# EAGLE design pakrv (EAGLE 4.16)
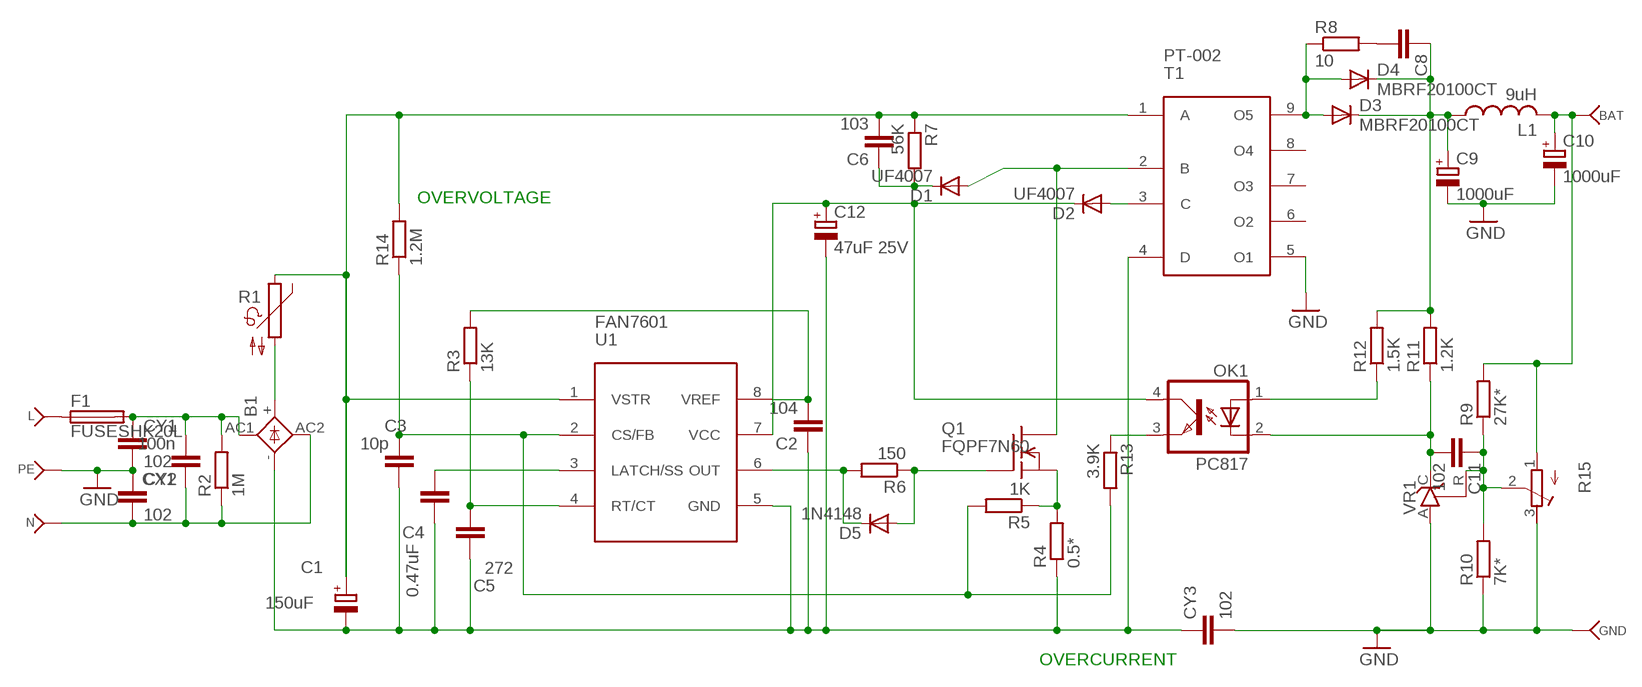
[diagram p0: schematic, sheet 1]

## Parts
B1  2KBB-R  [2KBB-R]
BAT  PINA  [PIN2]
C1  150uF  CPOL-EUE7.5-16  [E7,5-16]
C2  104  C-EU050-024X044  [C050-024X044]
C3  10p  C-EU050-024X044  [C050-024X044]
C4  0.47uF  C-EU050-024X044  [C050-024X044]
C5  272  C-EU050-024X044  [C050-024X044]
C6  103  C-EU075-032X103  [C075-032X103]
C8  C-EU050-024X044  [C050-024X044]
C9  1000uF  CPOL-EUE5-8.5  [E5-8,5]
C10  1000uF  CPOL-EUE5-8.5  [E5-8,5]
C11  102  C-EU025-024X044  [C025-024X044]
C12  47uF 25V  CPOL-EUE2.5-6  [E2,5-6]
CX1  100n  CXXC10B5  [XC10B5]
CY1  102  CYYC7B5  [YC7B5]
CY2  102  CYYC7B5  [YC7B5]
CY3  102  CYYC7B5  [YC7B5]
D1  UF4007  DIODE-DO07  [DO07]
D2  UF4007  DIODE-DO41-10  [DO41-10]
D3  MBRF20100CT  DIODE-DO220S  [DO220S]
D4  MBRF20100CT  DIODE-DO220S  [DO220S]
D5  1N4148  DIODE-DO35-10  [DO35-10]
F1  FUSESHK20L  [SHK20L]
GND  PINA  [PIN2]
L  PINA  [PIN2]
L1  9uH  L-US0207/7  [0207/7]
N  PINA  [PIN2]
OK1  PC817  [DIL04]
PE  PINA  [PIN2]
Q1  FQPF7N60  BUZ60  [TO220]
R1  B57164  [B57164]
R2  1M  R-EU_0207/15  [0207/15]
R3  13K  R-EU_0204/2V  [0204V]
R4  0.5*  R-EU_0207/10  [0207/10]
R5  1K  R-EU_0207/12  [0207/12]
R6  150  R-EU_0204/7  [0204/7]
R7  56K  R-EU_0414/5V  [0414V]
R8  10  R-EU_0204/2V  [0204V]
R9  27K*  R-EU_0204/5  [0204/5]
R10  7K*  R-EU_0204/5  [0204/5]
R11  1.2K  R-EU_0204/5  [0204/5]
R12  1.5K  R-EU_0204/5  [0204/5]
R13  3.9K  R-EU_0204/2V  [0204V]
R14  1.2M  R-EU_0204/2V  [0204V]
R15  R-TRIMM74X  [RTRIM74X]
T1  PT-002  [PT-002]
U1  FAN7601  [DIL08]
VR1  TL431CLP  [TO92-CLP]

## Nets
FEEDBACK: C3.2 R5.2 R13.2 R14.1 U1.2(CS/FB)
GATE: D5.A Q1.1(G) R6.1
GND: C9.- C10.- CY1.2 CY2.1 CY3.2 GND.P$1(P) PE.P$1(P) R10.1 R15.3(A) T1.5(O1) VR1.A
MINUS: B1.- C1.- C2.1 C3.1 C4.1 C5.1 C12.- CY3.1 R4.1 T1.4(D) U1.5(GND)
N$1: B1.+ R1.2
N$2: B1.AC1 CX1.2 CY1.1 F1.2A R2.2
N$5: B1.AC2 CX1.1 CY2.2 N.P$1(P) R2.1
N$6: D1.A Q1.2(D) T1.2(B)
N$7: C6.1 D1.C R7.2
N$8: C5.2 R3.1 U1.4(RT/CT)
N$9: C4.2 U1.3(LATCH/SS)
N$10: F1.1A L.P$1(P)
N$11: C2.2 R3.2 U1.8(VREF)
N$12: C11.2 OK1.2(C) R11.1 VR1.C
N$15: Q1.3(S) R4.2 R5.1
N$16: OK1.1(A) R12.1
N$17: C8.1 C9.+ D3.C D4.C L1.1 R11.2 R12.2
N$18: D2.A T1.3(C)
N$20: D3.A D4.A R8.1 T1.9(O5)
N$21: C11.1 R9.1 R10.2 R15.2(S) VR1.R
N$22: C8.2 R8.2
N$24: OK1.3(EMIT) R13.1
N$26: BAT.P$1(P) C10.+ L1.2 R9.2 R15.1(E)
OUT: D5.C R6.2 U1.6(OUT)
PLIUS: C1.+ C6.2 R1.1 R7.1 R14.2 T1.1(A) U1.1(VSTR)
VCC: C12.+ D2.C OK1.4(COL) U1.7(VCC)
Unconnected: T1.6(O2) T1.7(O3) T1.8(O4)

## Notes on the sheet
- OVERVOLTAGE
- OVERCURRENT

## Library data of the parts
B1 = rectifier:2KBB-R: RECTIFIER grid 3 x 5 mm
BAT GND L N PE = LevoROMS:PIN*: PIN
C1 C9 C10 C12 = rcl:CPOL-EU: POLARIZED CAPACITOR, European symbol
C2-C6 C8 C11 = rcl:C-EU: CAPACITOR, European symbol
CX1 = rcl:CX: X CAPACITOR
CY1-CY3 = rcl:CY: Y CAPACITOR
D1-D5 = diode:DIODE-: DIODE
F1 = fuse:FUSE: Fuse
L1 = rcl:L-US: INDUCTOR, American symbol
OK1 = optocoupler:PC817: SHARP OPTO COUPLER
Q1 = transistor-fet:BUZ60: N-Channel Enhancement MOSFET 400V; 5,5A; 1,0Ohm
R1 = ptc-ntc:B57164: SIEMENS NTC
R2-R14 = rcl:R-EU_: RESISTOR, European symbol
R15 = rcl:R-TRIMM: Trimm resistor
T1 = LG-trafo:PT-002
U1 = LevoROMS:FAN7601
VR1 = v-reg:TL431CLP: VOLTAGE REGULATOR

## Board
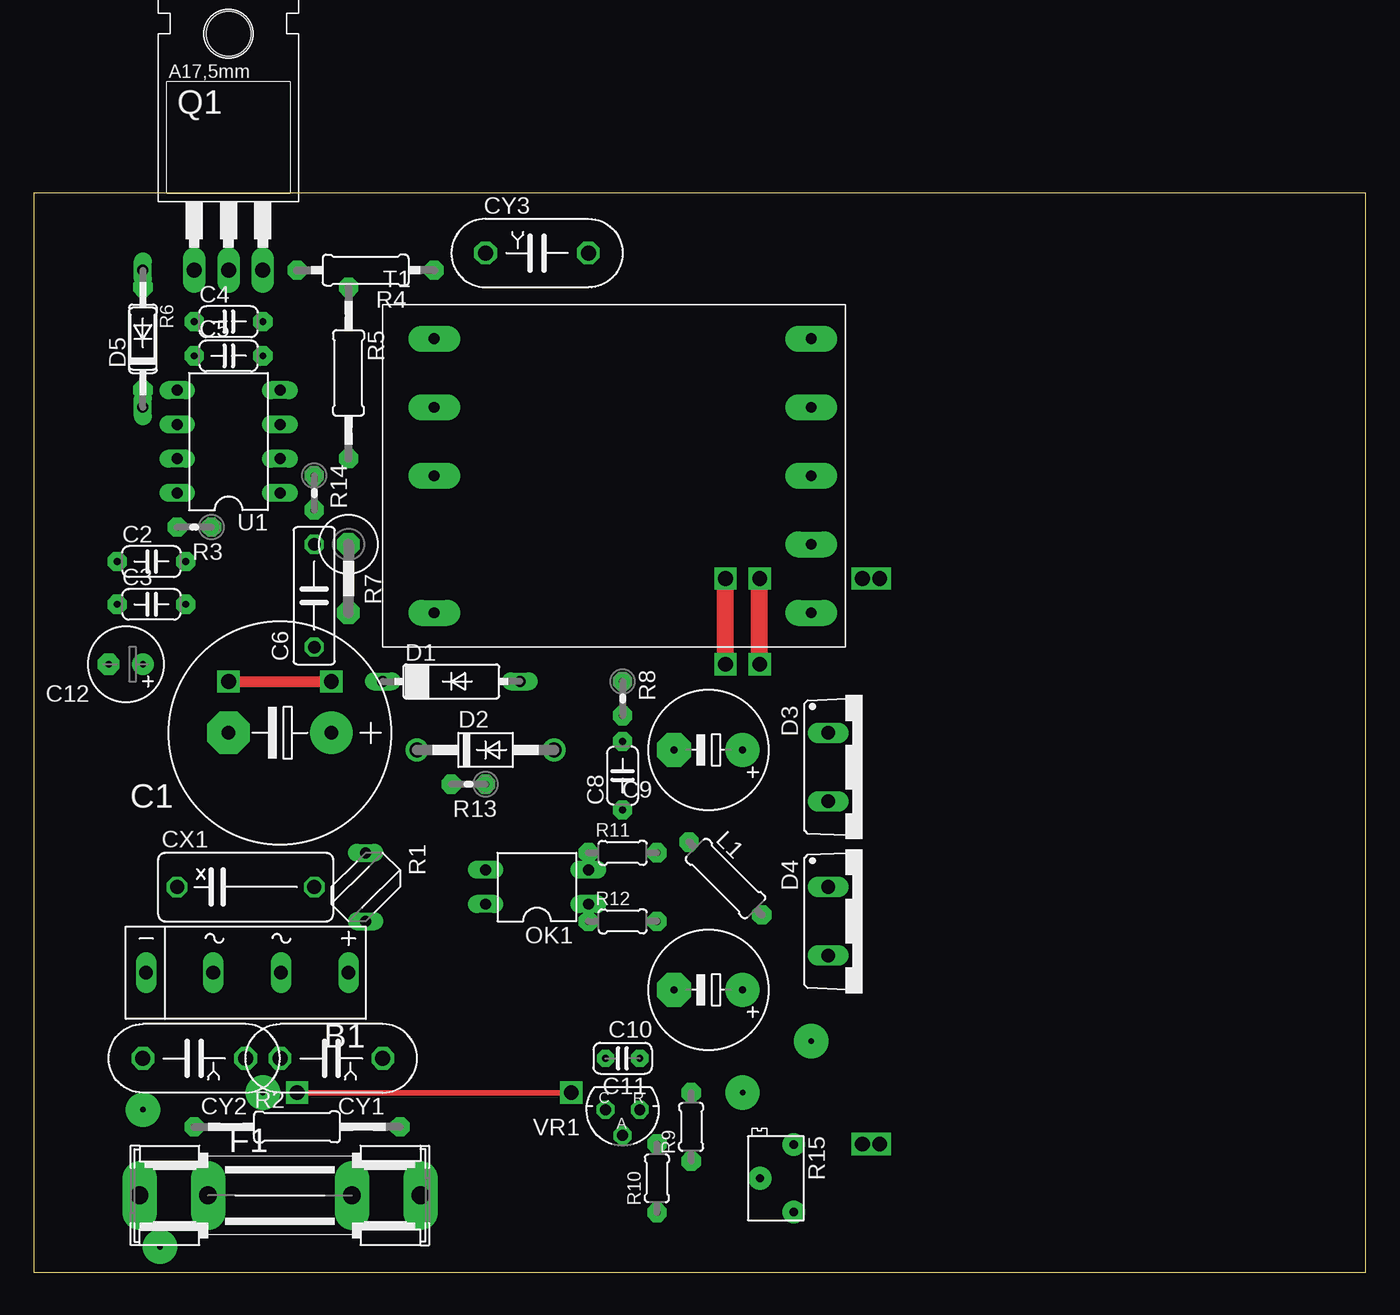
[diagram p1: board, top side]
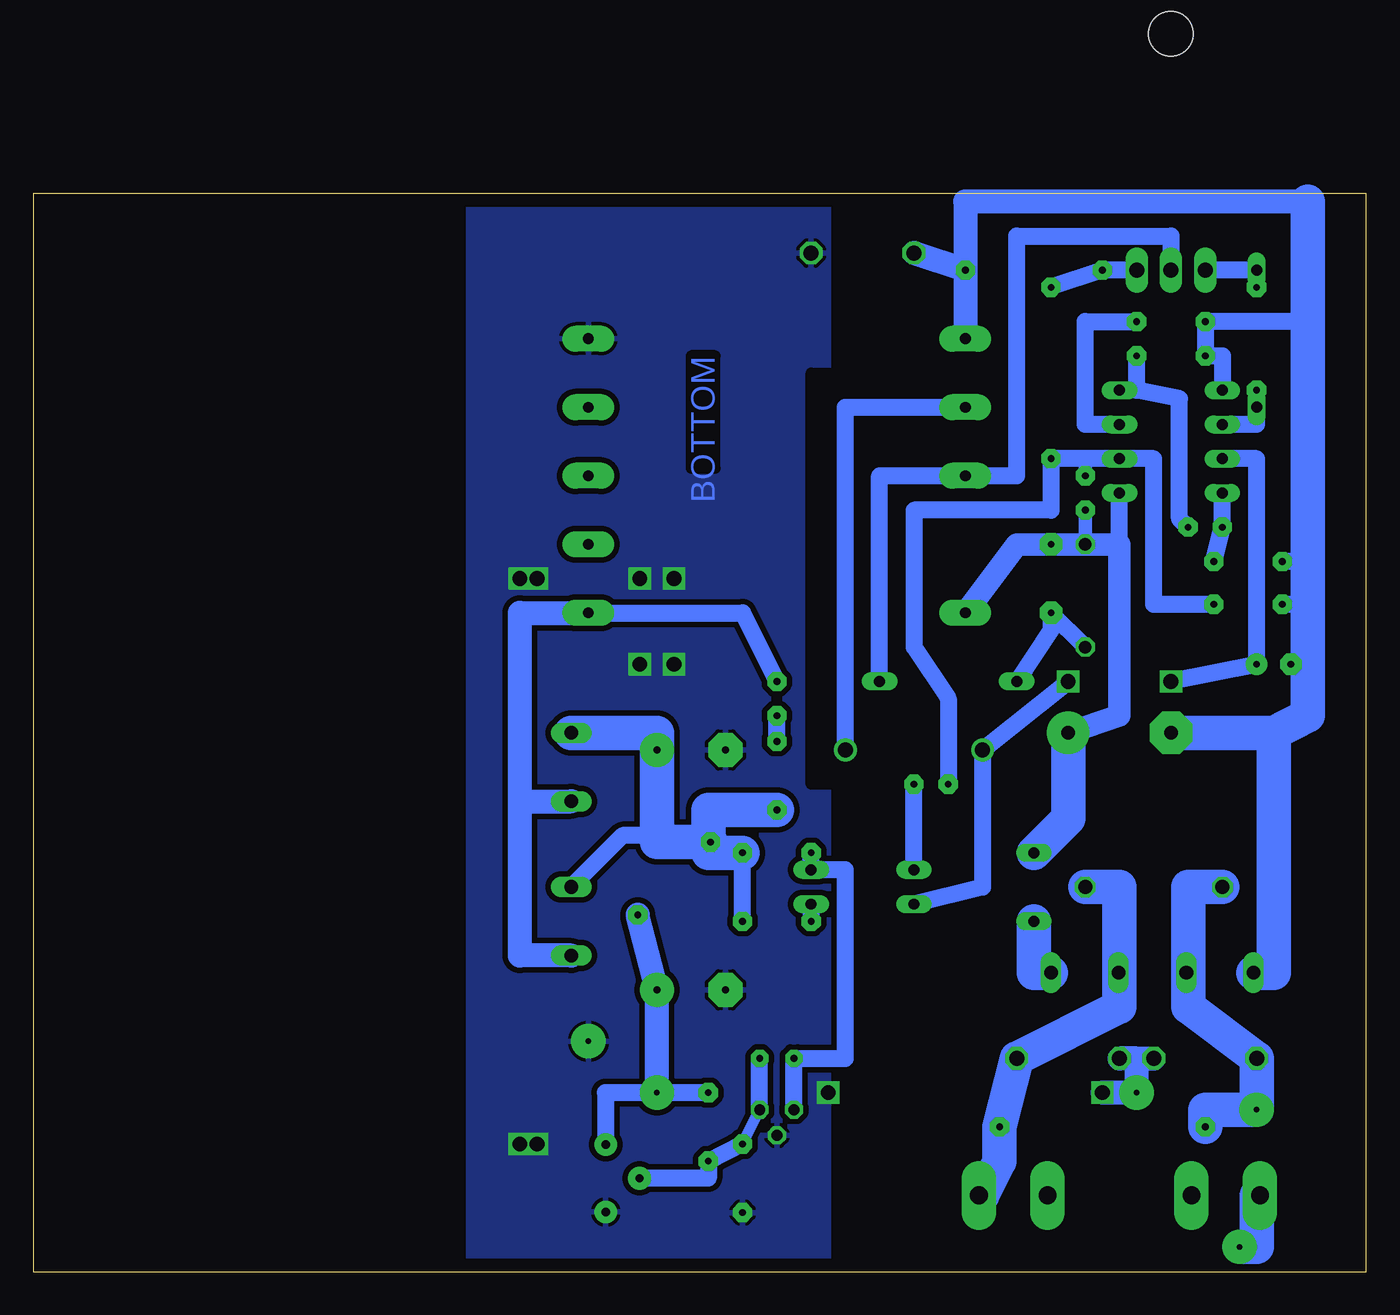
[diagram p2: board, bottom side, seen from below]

Size 98.73 x 80 mm. Coordinates in mm from the lower left corner, seen from the top.
Outline: 0,0 98.73,0 98.73,80 0,80 0,0
Copper layers (1*16): Top 0.035mm / dielectric 1.5mm / Bottom 0.035mm
Design rules "default": minimum track width 10mil, minimum drill 24mil, track to track 8mil, track to pad 8mil, pad to pad 8mil, via to via 8mil, smd to smd 8mil, copper to edge 40mil, drill to drill 8mil, minimum pad ring 10mil, minimum via ring 8mil, stop-mask expansion 4mil, vias tented up to drill 0mil, thermal gap 10mil
bRestrict: area 36,36.2 to 41.1,66.7

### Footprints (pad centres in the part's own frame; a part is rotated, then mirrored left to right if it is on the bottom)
2KBB-R = drill 1.016 long: + -7.62,0; - 7.391,0; AC1 -2.616,0; AC2 2.413,0
PIN2 = drill 0.406 pad 2.54 round: P$1 0,0
E7,5-16 = drill 1.016 pad 3.15 round: + -3.81,0 | drill 1.016 pad 3.15 octagon: - 3.81,0
C050-024X044 = drill 0.5 pad 1.422 octagon: 1 -2.54,0; 2 2.54,0
C075-032X103 = drill 0.914 octagon: 1 -3.81,0; 2 3.81,0
E5-8,5 = drill 0.5 pad 2.54 round: + -2.54,0 | drill 0.5 pad 2.54 octagon: - 2.54,0
C025-024X044 = drill 0.5 pad 1.27 octagon: 1 -1.27,0; 2 1.27,0
E2,5-6 = drill 0.5 pad 1.6 round: + -1.27,0 | drill 0.5 pad 1.6 octagon: - 1.27,0
XC10B5 = drill 1.016 octagon: 1 -5.08,0; 2 5.08,0
YC7B5 = drill 1.118 octagon: 1 -3.81,0; 2 3.81,0
DO07 = drill 0.813 long: A 5.08,0; C -5.08,0
DO41-10 = drill 1.118 round: A 5.08,0; C -5.08,0
DO220S = drill 1.016 long: A 2.54,-2.54; C -2.54,-2.54
DO35-10 = drill 0.813 long: A 5.08,0; C -5.08,0
SHK20L = drill 1.321 pad 2.54 long: 1A -10.414,0; 1B -5.334,0; 2A 10.414,0; 2B 5.334,0
0207/7 = drill 0.5 pad 1.422 octagon: 1 -3.81,0; 2 3.81,0
DIL04 = drill 0.813 long: 1 -1.27,-3.81; 2 1.27,-3.81; 3 1.27,3.81; 4 -1.27,3.81
TO220 = drill 1.118 long: 1 -2.54,-6.35; 2 0,-6.35; 3 2.54,-6.35 | hole 3.302: 0,11.176
B57164 = drill 0.813 long: 1 -2.54,0; 2 2.54,0
0207/15 = drill 0.5 pad 1.422 octagon: 1 -7.62,0; 2 7.62,0
0204V = drill 0.5 pad 1.422 octagon: 1 -1.27,0; 2 1.27,0
0207/10 = drill 0.5 pad 1.422 octagon: 1 -5.08,0; 2 5.08,0
0207/12 = drill 0.5 pad 1.422 octagon: 1 -6.35,0; 2 6.35,0
0204/7 = drill 0.5 pad 1.422 octagon: 1 -3.81,0; 2 3.81,0
0414V = drill 0.5 pad 1.676 octagon: 1 -2.54,0; 2 2.54,0
0204/5 = drill 0.5 pad 1.422 octagon: 1 -2.54,0; 2 2.54,0
RTRIM74X = drill 0.61 pad 1.676 round: 1 -1.25,-2.5; 2 1.25,0; 3 -1.25,2.5
PT-002 = drill 0.8 pad 1.93 long: 1 -3.81,-12.7; 2 -3.81,-2.54; 3 -3.81,2.54; 4 -3.81,7.62; 5 24.13,7.62; 6 24.13,2.54; 7 24.13,-2.54; 8 24.13,-7.62; 9 24.13,-12.7
DIL08 = drill 0.813 long: 1 -3.81,-3.81; 2 -1.27,-3.81; 3 1.27,-3.81; 4 3.81,-3.81; 5 3.81,3.81; 6 1.27,3.81; 7 -1.27,3.81; 8 -3.81,3.81
TO92-CLP = drill 0.813 octagon: A 0,1.905; C 1.27,0; R -1.27,0

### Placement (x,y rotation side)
B1  15.71,22.22 180 top
BAT  52.54,13.33 0 top
C1  18.25,40 180 top
C2  8.72,52.7 0 top
C3  8.72,49.53 0 top
C4  14.44,70.48 0 top
C5  14.44,67.94 0 top
C6  20.79,50.16 90 top
C8  43.65,36.83 90 top
C9  50,38.73 180 top
C10  50,20.95 180 top
C11  43.65,15.87 180 top
C12  6.82,45.08 180 top
CX1  15.71,28.57 0 top
CY1  22.06,15.87 180 top
CY2  11.9,15.87 180 top
CY3  37.3,75.56 0 top
D1  30.95,43.81 0 top
D2  33.49,38.73 0 top
D3  61.43,37.46 270 top
D4  61.43,26.03 270 top
D5  8.09,69.21 90 top
F1  18.25,5.71 0 top
GND  16.98,13.33 0 top
L  9.36,1.9 0 top
L1  51.27,29.2 315 top
N  8.09,12.06 0 top
OK1  37.3,28.57 90 top
PE  57.62,17.14 0 top
Q1  14.44,80.64 0 top
R1  24.6,28.57 270 top
R2  19.52,10.79 0 top
R3  11.9,55.24 180 top
R4  24.6,74.29 180 top
R5  23.33,66.67 270 top
R6  8.09,69.21 270 top
R7  23.33,51.43 270 top
R8  43.65,42.54 270 top
R9  48.73,10.79 90 top
R10  46.19,6.98 90 top
R11  43.65,31.11 0 top
R12  43.65,26.03 0 top
R13  32.22,36.19 180 top
R14  20.79,57.78 270 top
R15  55.08,6.98 180 top
T1  33.49,61.59 0 top
U1  14.44,61.59 90 top
VR1  43.65,12.06 180 top

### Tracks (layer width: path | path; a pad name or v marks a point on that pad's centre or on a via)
FEEDBACK
  Bottom 1.016: 20.79,60.32 R14.1
  Bottom 1.27: R13.2 30.95,42.54 33.49,46.35 33.49,56.51 23.33,56.51 R5.2 20.79,60.32 U1.2 15.71,60.32 15.71,49.53 C3.2
GATE
  Bottom 0.406: R6.1 D5.A
  Bottom 1.27: D5.A Q1.1
GND  (via drill 1.1, 1.1 pad 1.02)
  Top 0.406: v19.52,13.33 v39.84,13.33
  Top 1.27: v51.27,45.08 v51.27,51.43 | v53.81,45.08 v53.81,51.43
  Bottom 1.778: 16.98,15.87 CY2.1 | 16.98,15.87 CY1.2 | 16.98,15.87 GND.P$1 v19.52,13.33
  other vias: 61.43,51.43 62.7,51.43 61.43,9.52 62.7,9.52
  pour Bottom (isolate 0.406): 39.84,81.91 39.84,-1.91 66.51,-1.91 66.51,81.91
MINUS
  Bottom 0.813: 4.28,50.16 5.55,49.53
  Bottom 1.27: U1.5 10.63,67.94 C5.1 C4.1 4.28,70.48 | 4.28,52.7 C2.1 | 5.55,49.53 C3.1 | 4.28,45.08 C12.-
  Bottom 1.778: R4.1 CY3.1 | R4.1 T1.4 | 4.28,79.37 29.68,79.37 R4.1
  Bottom 2.54: 6.82,40 C1.- | 6.82,40 6.82,22.22 B1.- | 4.28,79.37 4.28,70.48 4.28,52.7 4.28,50.16 4.28,45.08 4.28,41.27 6.82,40
N$1
  Bottom 2.54: B1.+ 24.6,22.22 R1.2
N$2
  Bottom 0.406: F1.2A 28.41,5.71 | 18.25,22.22 B1.AC1
  Bottom 2.54: CX1.2 18.25,28.57 18.25,22.22 18.25,19.68 CY1.1 R2.2 27.14,8.25 28.41,5.71
N$5
  Bottom 0.406: 13.17,22.22 B1.AC2
  Bottom 2.54: CX1.1 13.17,28.57 13.17,22.22 13.17,19.68 CY2.2 N.P$1 11.9,12.06 R2.1
N$6
  Bottom 1.27: D1.A 36.03,59.05 T1.2 25.87,59.05 25.87,76.83 14.44,76.83 Q1.2
N$7
  Bottom 1.27: C6.1 R7.2 23.33,47.62 D1.C
N$8
  Bottom 1.27: 16.98,65.4 U1.4 | 16.98,65.4 C5.2 | R3.1 13.8,55.88 13.8,64.77 16.98,65.4
N$9
  Bottom 1.27: U1.3 20.79,62.86 20.79,70.48 C4.2
N$10
  Bottom 0.813: 8.09,5.71 F1.1A
  Bottom 2.54: L.P$1 8.09,1.9 8.09,5.71
N$11
  Bottom 1.27: U1.8 R3.2 C2.2
N$12
  Bottom 1.27: R11.1 OK1.2 38.57,29.84 38.57,15.87 C11.2 VR1.C
N$15
  Bottom 1.27: Q1.3 R4.2 R5.1
N$16
  Bottom 1.27: OK1.1 R12.1
N$17
  Bottom 1.27: R12.2 R11.2 | D4.C 55.08,32.38 52.54,32.38
  Bottom 2.54: C8.1 48.73,34.29 48.73,32.38 | 48.73,32.38 48.73,31.9 L1.1 52.54,31.9 52.54,32.38 C9.+ 52.54,40 D3.C | R11.2 48.73,31.11 48.73,32.38
N$18
  Bottom 1.27: T1.3 38.57,64.13 D2.A
N$20
  Bottom 1.27: T1.9 46.19,48.89 R8.1
  Bottom 1.778: D4.A 62.7,23.49 62.7,34.92 | 62.7,34.92 62.7,48.89 T1.9 | 62.7,34.92 D3.A
N$21
  Bottom 0.813: R10.2 VR1.R
  Bottom 1.27: VR1.R C11.1 | R10.2 R9.1 48.73,6.98 R15.2
N$22
  Bottom 1.27: C8.2 R8.2
N$24
  Bottom 1.27: OK1.3 R13.1
N$26
  Bottom 1.27: R9.2 BAT.P$1 56.35,13.33 56.33,13.31 R15.1
  Bottom 1.778: L1.2 C10.+ BAT.P$1
OUT
  Bottom 0.406: D5.C R6.2
  Bottom 1.27: D5.C 8.09,62.86 U1.6
PLIUS
  Bottom 1.016: C6.2 R14.2
  Bottom 1.27: 18.25,53.97 U1.1
  Bottom 1.676: C1.+ 18.25,41.27 18.25,53.97 C6.2 R7.1 25.87,53.97 T1.1
  Bottom 2.54: R1.1 22.06,33.65 C1.+
VCC  (via drill 1.1, 1.1 pad 1.02)
  Top 0.813: v14.44,43.81 v22.06,43.81
  Bottom 1.27: v22.06,43.81 D2.C 28.41,28.57 OK1.4 | U1.7 8.09,60.32 C12.+ v14.44,43.81

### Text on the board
Bottom: BOTTOM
